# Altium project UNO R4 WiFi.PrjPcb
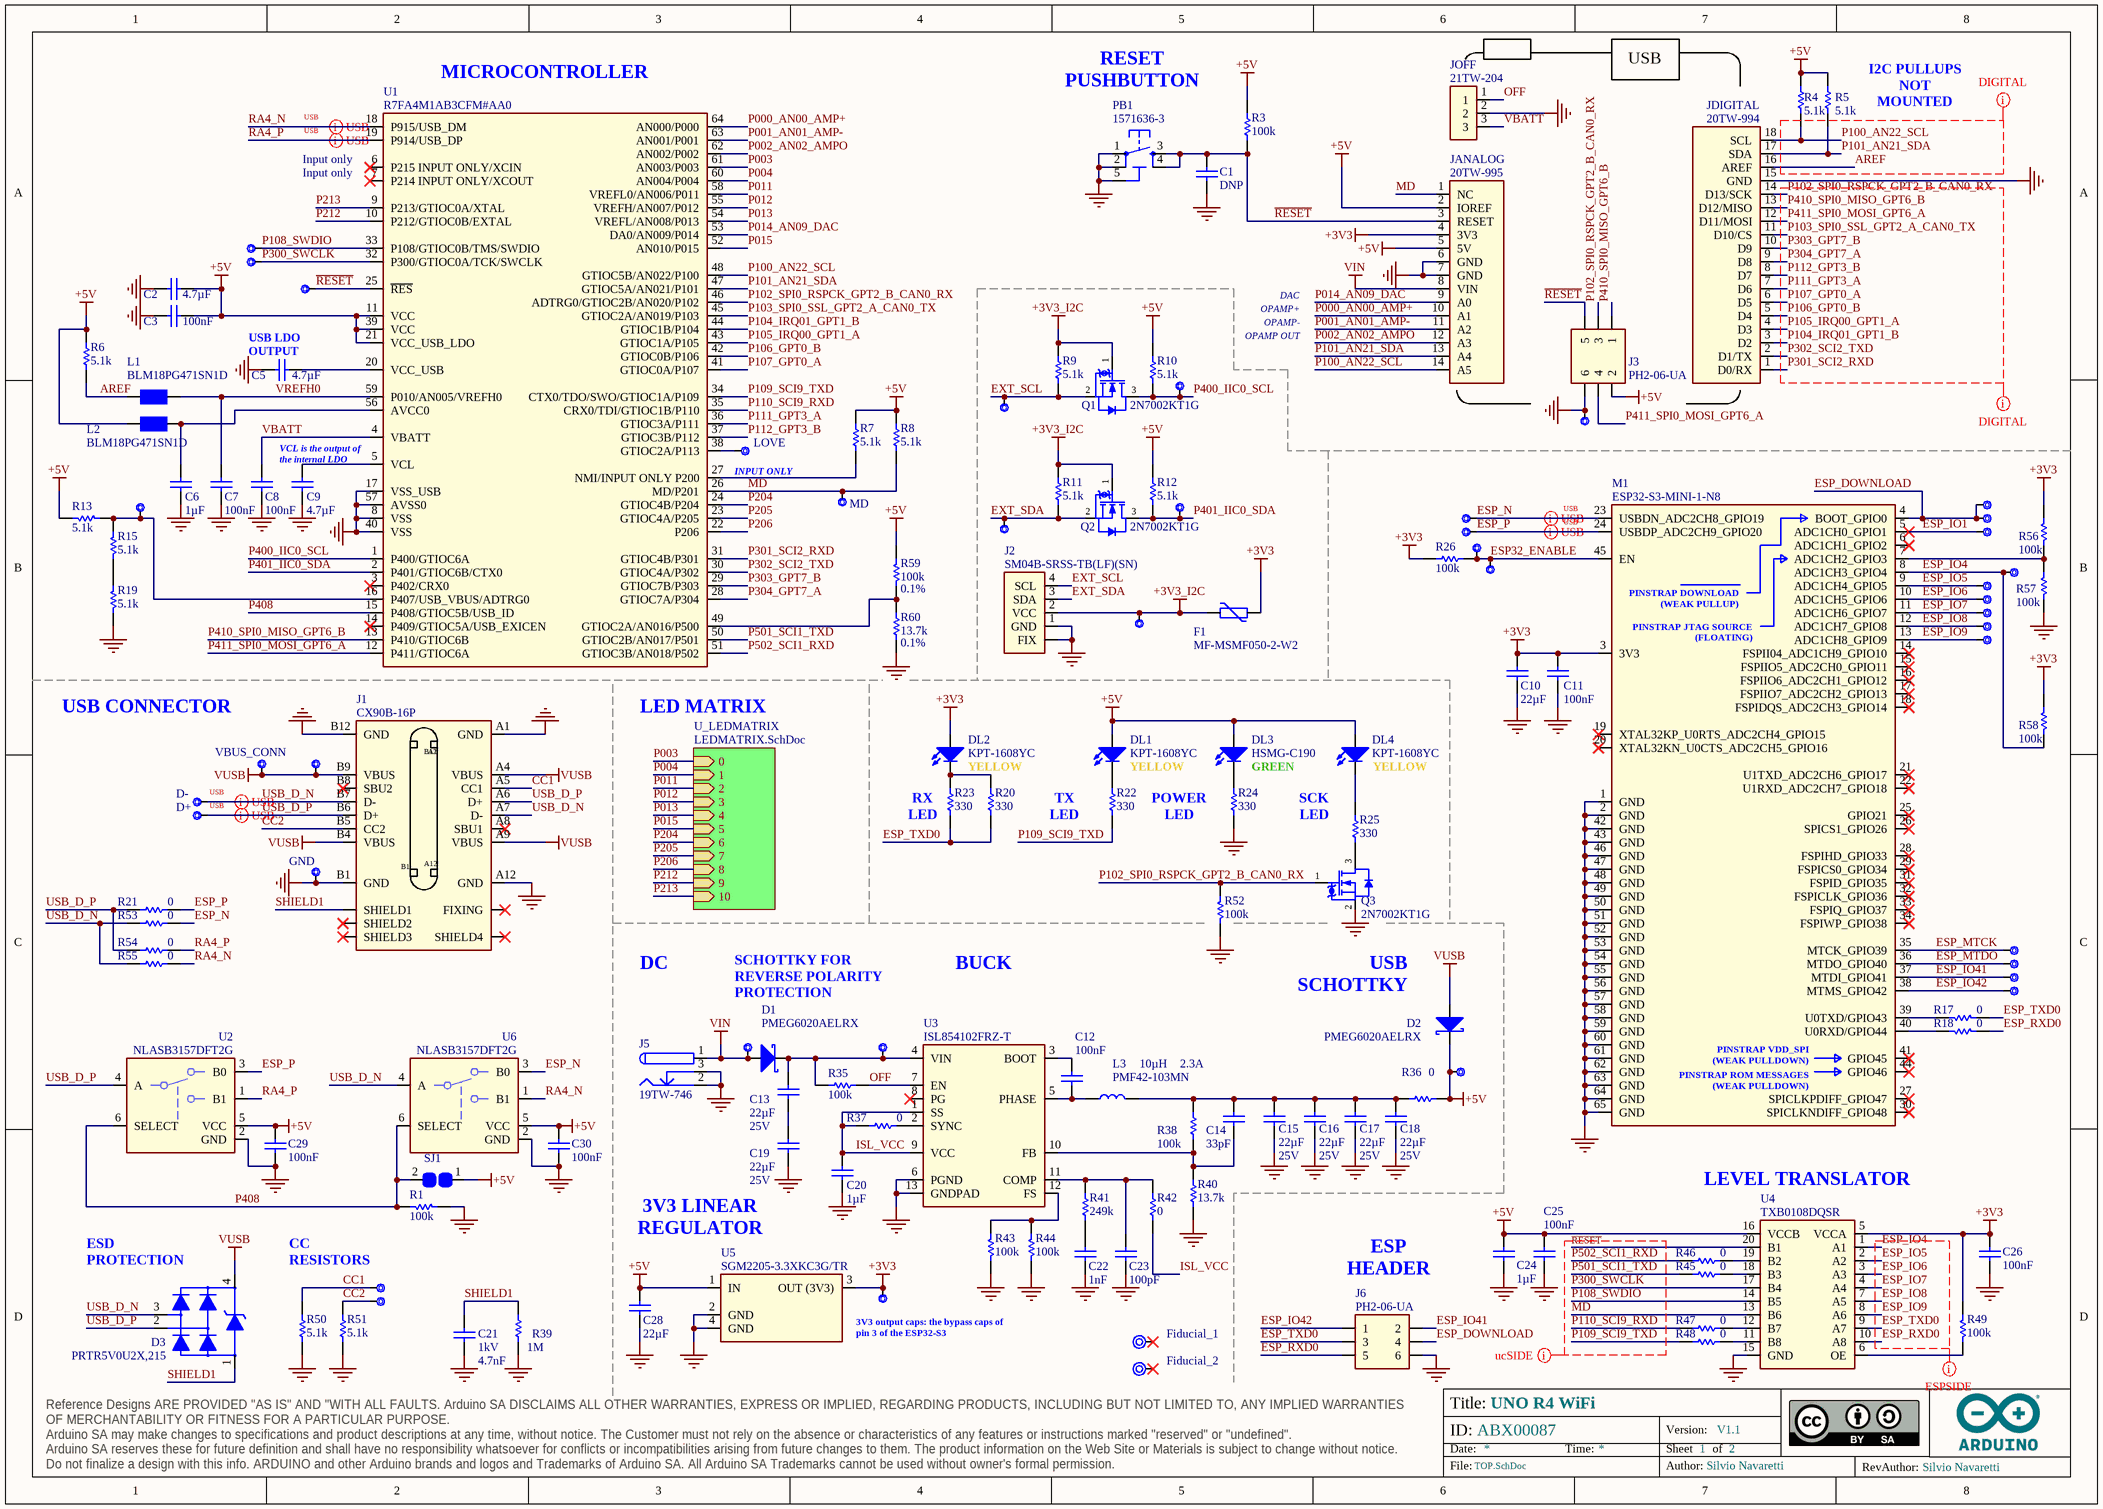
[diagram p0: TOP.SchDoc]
Version: V1.1; VIA_THROUGH_PAD_MM: 0.6; VIA_THROUGH_HOLE_MM: 0.3; VIA_THROUGH: X; VIA_5_PAD_MM: _; VIA_5_HOLE_MM: _; VIA_5: _; VIA_4_PAD_MM: _; VIA_4_HOLE_MM: _; VIA_4: _; VIA_3_PAD_MM: _; VIA_3_HOLE_MM: _; VIA_3: _; VIA_2_PAD_MM: _; VIA_2_HOLE_MM: _; VIA_2: _; VIA_1_PAD_MM: _; VIA_1_HOLE_MM: _; VIA_1: _; TRACK_MIN_WIDTH_OUTER: 0.15mm; TRACK_MIN_WIDTH_INNER: 0.15mm; SKU: ABX00087; PANEL_TABS: _; PANEL_SIZE: 284.7mm x 157.16mm; PANEL_SCORING: X; PANEL_REQUESTED: _; PANEL_PROVIDED: X; PANEL_NUMBER_OF_FIGURES: 10; PANEL_NOT_REQUESTED: _; PANEL_MILLING: X; INSULATION_MIN_OUTER: 0.15mm; INSULATION_MIN_INNER: 0.15mm; FINISH_TBD: _; FINISH_TABS: _; FINISH_SOLDERMASK_TOP: X; FINISH_SOLDERMASK_PEELABLE_TOP: _; FINISH_SOLDERMASK_PEELABLE_COLOR: _; FINISH_SOLDERMASK_PEELABLE_BOTTOM: _; FINISH_SOLDERMASK_COLOR: BLUE; FINISH_SOLDERMASK_BOTTOM: X; FINISH_SN/PB: _; FINISH_SILK_TOP: X; FINISH_SILK_COLOR: WHITE; FINISH_SILK_BOTTOM: X; FINISH_NI/AU: _; FINISH_HAL_LF: _; FINISH_HAL: _; FINISH_ENIG: X; FINISH_EDGE_PLATING: _; FINISH_ADJUSTMENTS: _; DRILLS_SOLDER_FILLING: X; DRILLS_SLOT: _; DRILLS_RESIN_FILLING: _; DRILLS_PRESSFIT: _; DRILLS_LASER: _; DRILLS_FULL: X; DRILLS_COPPER_FILLING: _; DRILLS_BURIED: _; DRILLS_BLIND: _; BOARD_INFO_THICKNESS: 1.6mm; BOARD_INFO_TBD: _; BOARD_INFO_RIGID/FLEX: _; BOARD_INFO_RIGID: X; BOARD_INFO_POLYMIDE: _; BOARD_INFO_PCB_SIZE: 68.58mm x 53.34mm; BOARD_INFO_NUMBER_OF_LAYERS: 4; BOARD_INFO_IPC_NA: X; BOARD_INFO_IPC3: _; BOARD_INFO_IPC2: _; BOARD_INFO_IPC1: _; BOARD_INFO_FR4_HTG: _; BOARD_INFO_FR4: X; BOARD_INFO_FLEX: _; BOARD_INFO_Er: _; BOARD_INFO_AUTHOR: Silvio Navaretti; ASSEMBLY_THT: X; ASSEMBLY_SMD: X; ASSEMBLY_PRESSFIT: _; ASSEMBLY_BGA: _
2 sheets, 257 parts. Net scope: hierarchical (ports join the sheet entries above them; power ports are global).
Board file: PCB.PcbDoc
Sheets:
  TOP.SchDoc
    U_LEDMATRIX = LEDMATRIX.SchDoc

## Sheet TOP.SchDoc: UNO R4 WiFi
size A3; Author: Silvio Navaretti; CompanyName: ARDUINO SRL; DrawnBy: Silvio Navaretti; Engineer: Silvio Navaretti; Organization: ARDUINO SRL; Address1: Via Agostino Da Montefeltro 2 Torino TO, Italy; DocumentNumber: ABX00087; Revision: V1.1; SheetNumber: 1; SheetTotal: 2; RevAuthor: Silvio Navaretti

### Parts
3V3_IC  CMP-018-0004-A.4  [TP-0.8MM]  (value not drawn)  (no BOM)
3V3_TOP  CMP-018-0004-A.4  [TP-0.8MM]  (value not drawn)  (no BOM)
5V_TOP  CMP-018-0004-A.4  [TP-0.8MM]  (value not drawn)  (no BOM)
BUCK_IN_TOP  CMP-018-0004-A.4  [TP-0.8MM]  (value not drawn)  (no BOM)
C1  DNP  [CAP-0402]
C2  value 4.7µF  [CAP-0603]  (hidden comment: GRM188R61C475KAAJD)
C3  value 100nF  [CAP-0402]  (hidden comment: GRM155R61H104KE19D)
C5  value 4.7µF  [CAP-0603]  (hidden comment: GRM188R61C475KAAJD)
C6  value 1µF  [CAP-0402]  (hidden comment: CL05A105KP5NNNC)
C7  value 100nF  [CAP-0402]  (hidden comment: GRM155R61H104KE19D)
C8  value 100nF  [CAP-0402]  (hidden comment: GRM155R61H104KE19D)
C9  value 4.7µF  [CAP-0603]  (hidden comment: GRM188R61C475KAAJD)
C10  value 22µF  [CAP-0805]  (hidden comment: CL21A226MAQNNNE)
C11  value 100nF  [CAP-0402]  (hidden comment: GRM155R61H104KE19D)
C12  value 100nF  [CAP-0402]  (hidden comment: GRM155R61H104KE19D)
C13  value 22µF  Voltage: 25V  [CAP-0805]  (hidden comment: CL21A226MAQNNNE)
C14  value 33pF  [CAP-0402]  (hidden comment: GRM1555C1H330JA01D)
C15  value 22µF  Voltage: 25V  [CAP-0805]  (hidden comment: CL21A226MAQNNNE)
C16  value 22µF  Voltage: 25V  [CAP-0805]  (hidden comment: CL21A226MAQNNNE)
C17  value 22µF  Voltage: 25V  [CAP-0805]  (hidden comment: CL21A226MAQNNNE)
C18  value 22µF  Voltage: 25V  [CAP-0805]  (hidden comment: CL21A226MAQNNNE)
C19  value 22µF  Voltage: 25V  [CAP-0805]  (hidden comment: CL21A226MAQNNNE)
C20  value 1µF  [CAP-0402]  (hidden comment: CL05A105KP5NNNC)
C21  value 4.7nF  Voltage: 1kV  [CAP-0805]  (hidden comment: FV21X472K102ECG)
C22  value 1nF  [CAP-0402]  (hidden comment: GRM155R71H102KA01D)
C23  value 100pF  [CAP-0402]  (hidden comment: CC0402JRNPO9BN101)
C24  value 1µF  [CAP-0402]  (hidden comment: CL05A105KP5NNNC)
C25  value 100nF  [CAP-0402]  (hidden comment: GRM155R61H104KE19D)
C26  value 100nF  [CAP-0402]  (hidden comment: GRM155R61H104KE19D)
C28  value 22µF  [CAP-0805]  (hidden comment: CL21A226MAQNNNE)
C29  value 100nF  [CAP-0402]  (hidden comment: GRM155R61H104KE19D)
C30  value 100nF  [CAP-0402]  (hidden comment: GRM155R61H104KE19D)
CC1  CMP-018-0004-A.4  [TP-0.8MM]  (value not drawn)  (no BOM)
CC2  CMP-018-0004-A.4  [TP-0.8MM]  (value not drawn)  (no BOM)
D1  PMEG6020AELRX  [SOD123-1]
D2  PMEG6020AELRX  [SOD123-1]
D3  PRTR5V0U2X,215  [SOT190P230X110-4N]
D+  CMP-018-0005-A.3  [TP-1.00MM]  (value not drawn)  (no BOM)
D+_TOP  CMP-018-0004-A.4  [TP-0.8MM]  (value not drawn)  (no BOM)
D-  CMP-018-0005-A.3  [TP-1.00MM]  (value not drawn)  (no BOM)
D-_TOP  CMP-018-0004-A.4  [TP-0.8MM]  (value not drawn)  (no BOM)
DL1  KPT-1608YC  [LEDC1608X80N-AK]
DL2  KPT-1608YC  [LEDC1608X80N-AK]
DL3  HSMG-C190  [LEDC1608X80N-AK]
DL4  KPT-1608YC  [LEDC1608X80N-AK]
ESP_DOWNLOAD_BOTTOM1  CMP-018-0005-A.3  [TP-1.00MM]  (value not drawn)  (no BOM)
ESP_DOWNLOAD_TOP  CMP-018-0004-A.4  [TP-0.8MM]  (value not drawn)  (no BOM)
ESP_EN_BOTTOM  CMP-018-0005-A.3  [TP-1.00MM]  (value not drawn)  (no BOM)
ESP_EN_TOP  CMP-018-0004-A.4  [TP-0.8MM]  (value not drawn)  (no BOM)
ESP_IO1  CMP-018-0004-A.4  [TP-0.8MM]  (value not drawn)  (no BOM)
ESP_IO4  CMP-018-0004-A.4  [TP-0.8MM]  (value not drawn)  (no BOM)
ESP_IO5  CMP-018-0004-A.4  [TP-0.8MM]  (value not drawn)  (no BOM)
ESP_IO6  CMP-018-0004-A.4  [TP-0.8MM]  (value not drawn)  (no BOM)
ESP_IO7  CMP-018-0004-A.4  [TP-0.8MM]  (value not drawn)  (no BOM)
ESP_IO8  CMP-018-0004-A.4  [TP-0.8MM]  (value not drawn)  (no BOM)
ESP_IO9  CMP-018-0004-A.4  [TP-0.8MM]  (value not drawn)  (no BOM)
ESP_MTCK  CMP-018-0004-A.4  [TP-0.8MM]  (value not drawn)  (no BOM)
ESP_MTDI  CMP-018-0004-A.4  [TP-0.8MM]  (value not drawn)  (no BOM)
ESP_MTDO  CMP-018-0004-A.4  [TP-0.8MM]  (value not drawn)  (no BOM)
ESP_MTMS  CMP-018-0004-A.4  [TP-0.8MM]  (value not drawn)  (no BOM)
EXT_SCL  CMP-018-0004-A.4  [TP-0.8MM]  (value not drawn)  (no BOM)
EXT_SDA  CMP-018-0004-A.4  [TP-0.8MM]  (value not drawn)  (no BOM)
F1  MF-MSMF050-2-W2  [1812]
Fiducial_1  Fiducial mark 1mm with 2mm solder  [Fiducial mark 1mm with circle-Footprint-1]  (value not drawn)  (no BOM)
Fiducial_2  Fiducial mark 1mm with 2mm solder  [Fiducial mark 1mm with circle-Footprint-1]  (value not drawn)  (no BOM)
GND  CMP-018-0005-A.3  [TP-1.00MM]  (value not drawn)  (no BOM)
GND2  CMP-018-0005-A.3  [TP-1.00MM]  (value not drawn)  (no BOM)
J1  CX90B-16P  [CX90B-16P-Footprint-1]
J2  SM04B-SRSS-TB(LF)(SN)  [SM04B-SRSS-TB(LF)(SN)-Footprint-1]
J3  PH2-06-UA  [2X03]
J5  19TW-746  [POWERSUPPLY_DC-21MM]
J6  PH2-06-UA  [2X03]
JANALOG  20TW-995  [1X14-CUSTOM]
JDIGITAL  20TW-994  [1X18-CUSTOM]
JOFF  21TW-204  [21TW-204]
L1  BLM18PG471SN1D  [L-0603]
L2  BLM18PG471SN1D  [L-0603]
L3  PMF42-103MN  Max DC Current: 2.3A  Inductance: 10µH  [PMF42]
LOVE  CMP-018-0005-A.3  [TP-1.00MM]  (value not drawn)  (no BOM)
M1  ESP32-S3-MINI-1-N8  [ESP32-S3-MINI-1-N8]
MD  CMP-018-0004-A.4  [TP-0.8MM]  (value not drawn)  (no BOM)
P400_SCL  CMP-018-0004-A.4  [TP-0.8MM]  (value not drawn)  (no BOM)
P401_SDA  CMP-018-0004-A.4  [TP-0.8MM]  (value not drawn)  (no BOM)
PB1  1571636-3  [TS42]
Q1  2N7002KT1G  [SOT23]
Q2  2N7002KT1G  [SOT23]
Q3  2N7002KT1G  [SOT23]
R1  value 100k  [RES-0402]  (hidden comment: CRCW0402100KFKEDC)
R3  value 100k  [RES-0402]  (hidden comment: CRCW0402100KFKEDC)
R4  value 5.1k  [RES-0402]  (hidden comment: RC0402FR-075K1L)
R5  value 5.1k  [RES-0402]  (hidden comment: RC0402FR-075K1L)
R6  value 5.1k  [RES-0402]  (hidden comment: RC0402FR-075K1L)
R7  value 5.1k  [RES-0402]  (hidden comment: RC0402FR-075K1L)
R8  value 5.1k  [RES-0402]  (hidden comment: RC0402FR-075K1L)
R9  value 5.1k  [RES-0402]  (hidden comment: RC0402FR-075K1L)
R10  value 5.1k  [RES-0402]  (hidden comment: RC0402FR-075K1L)
R11  value 5.1k  [RES-0402]  (hidden comment: RC0402FR-075K1L)
R12  value 5.1k  [RES-0402]  (hidden comment: RC0402FR-075K1L)
R13  value 5.1k  [RES-0402]  (hidden comment: RC0402FR-075K1L)
R15  value 5.1k  [RES-0402]  (hidden comment: RC0402FR-075K1L)
R17  value 0  [RES-0402]  (hidden comment: CRCW04020000Z0EDC)
R18  value 0  [RES-0402]  (hidden comment: CRCW04020000Z0EDC)
R19  value 5.1k  [RES-0402]  (hidden comment: RC0402FR-075K1L)
R20  value 330  [RES-0402]  (hidden comment: CRCW0402330RJNED)
R21  value 0  [RES-0402]  (hidden comment: CRCW04020000Z0EDC)
R22  value 330  [RES-0402]  (hidden comment: CRCW0402330RJNED)
R23  value 330  [RES-0402]  (hidden comment: CRCW0402330RJNED)
R24  value 330  [RES-0402]  (hidden comment: CRCW0402330RJNED)
R25  value 330  [RES-0402]  (hidden comment: CRCW0402330RJNED)
R26  value 100k  [RES-0402]  (hidden comment: CRCW0402100KFKEDC)
R35  value 100k  [RES-0402]  (hidden comment: CRCW0402100KFKEDC)
R36  value 0  [RES-0402]  (hidden comment: CRCW04020000Z0EDC)
R37  value 0  [RES-0402]  (hidden comment: CRCW04020000Z0EDC)
R38  value 100k  [RES-0402]  (hidden comment: CRCW0402100KFKEDC)
R39  value 1M  [RES-0402]  (hidden comment: CRCW04021M00FKED)
R40  value 13.7k  [RES-0402]  (hidden comment: RC0402FR-0713K7L)
R41  value 249k  [RES-0402]  (hidden comment: AC0402FR-07249KL)
R42  value 0  [RES-0402]  (hidden comment: CRCW04020000Z0EDC)
R43  value 100k  [RES-0402]  (hidden comment: CRCW0402100KFKEDC)
R44  value 100k  [RES-0402]  (hidden comment: CRCW0402100KFKEDC)
R45  value 0  [RES-0402]  (hidden comment: CRCW04020000Z0EDC)
R46  value 0  [RES-0402]  (hidden comment: CRCW04020000Z0EDC)
R47  value 0  [RES-0402]  (hidden comment: CRCW04020000Z0EDC)
R48  value 0  [RES-0402]  (hidden comment: CRCW04020000Z0EDC)
R49  value 100k  [RES-0402]  (hidden comment: CRCW0402100KFKEDC)
R50  value 5.1k  [RES-0402]  (hidden comment: RC0402FR-075K1L)
R51  value 5.1k  [RES-0402]  (hidden comment: RC0402FR-075K1L)
R52  value 100k  [RES-0402]  (hidden comment: CRCW0402100KFKEDC)
R53  value 0  [RES-0402]  (hidden comment: CRCW04020000Z0EDC)
R54  value 0  [RES-0402]  (hidden comment: CRCW04020000Z0EDC)
R55  value 0  [RES-0402]  (hidden comment: CRCW04020000Z0EDC)
R56  value 100k  [RES-0402]  (hidden comment: CRCW0402100KFKEDC)
R57  value 100k  [RES-0402]  (hidden comment: CRCW0402100KFKEDC)
R58  value 100k  [RES-0402]  (hidden comment: CRCW0402100KFKEDC)
R59  value 100k  Tolerance: 0.1%  [RES-0402]  (hidden comment: WF04H1003BT)
R60  value 13.7k  Tolerance: 0.1%  [RES-0402]  (hidden comment: WF04H1372BTL)
RES  CMP-018-0004-A.4  [TP-0.8MM]  (value not drawn)  (no BOM)
SJ1  SMD solder JUMPER 0805  [SJ]  (value not drawn)  (no BOM)
SWCLK  CMP-018-0004-A.4  [TP-0.8MM]  (value not drawn)  (no BOM)
SWDIO  CMP-018-0004-A.4  [TP-0.8MM]  (value not drawn)  (no BOM)
U1  R7FA4M1AB3CFM#AA0  [CQFP50P1200X1200X170-64L]
U2  NLASB3157DFT2G  [TSOP65P210X110-6N]
U3  ISL854102FRZ-T  [QFN0P300X400X100_HS-13L]
U4  TXB0108DQSR  [FP-DQS0020A-MFG]
U5  SGM2205-3.3XKC3G/TR  [SOT223-3]
U6  NLASB3157DFT2G  [TSOP65P210X110-6N]
uC_VBUS  CMP-018-0004-A.4  [TP-0.8MM]  (value not drawn)  (no BOM)
VBUS_CONN  CMP-018-0005-A.3  [TP-1.00MM]  (value not drawn)  (no BOM)
VCONN_TOP  CMP-018-0004-A.4  [TP-0.8MM]  (value not drawn)  (no BOM)
VIN_TOP  CMP-018-0004-A.4  [TP-0.8MM]  (value not drawn)  (no BOM)

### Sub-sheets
U_LEDMATRIX = LEDMATRIX.SchDoc: 0 (in), 1 (in), 2 (in), 3 (in), 4 (in), 5 (in), 6 (in), 7 (in), 8 (in), 9 (in), 10 (in)

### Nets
+3V3: 3V3_TOP.X C10.2 C11.2 C26.2 DL2.A F1.2 JANALOG.4(3V3) M1.3(3V3) R26.1 R49.2 R56.2 R58.2 U4.5(VCCA) U5.3(OUT_(3V3))
+3V3_I2C: 3V3_IC.X F1.1 J2.2(VCC) Q1.1(G) Q2.1(G) R9.1 R11.1
+5V: 5V_TOP.X C2.2 C3.2 C24.2 C25.2 C28.2 C29.2 C30.2 D2.C DL1.A DL3.A DL4.A J3.2 JANALOG.2(IOREF) JANALOG.5(5V) L2.1 R3.2 R4.2 R5.2 R6.2 R7.1 R8.1 R10.1 R12.1 R13.1 R36.2 R59.2 SJ1.1 U1.11(VCC) U1.21(VCC_USB_LDO) U1.39(VCC) U2.5(VCC) U4.16(VCCB) U5.1(IN) U6.5(VCC)
GND: C1.2 C2.1 C3.1 C5.1 C6.2 C7.1 C8.1 C9.1 C10.1 C11.1 C15.1 C16.1 C17.1 C18.1 C19.1 C20.2 C21.1 C22.1 C23.1 C24.1 C25.1 C26.1 C28.1 C29.1 C30.1 GND.X GND2.X J1.A1(GND) J1.A12(GND) J1.B1(GND) J1.B12(GND) J2.1(GND) J2.FIX J3.6 J5.2 J5.3 J6.6 JANALOG.6(GND) JANALOG.7(GND) JDIGITAL.15(GND) JOFF.2 M1.1(GND) M1.2(GND) M1.42(GND) M1.43(GND) M1.46(GND) M1.47(GND) M1.48(GND) M1.49(GND) M1.50(GND) M1.51(GND) M1.52(GND) M1.53(GND) M1.54(GND) M1.55(GND) M1.56(GND) M1.57(GND) M1.58(GND) M1.59(GND) M1.60(GND) M1.61(GND) M1.62(GND) M1.63(GND) M1.64(GND) M1.65(GND) PB1.1 PB1.2 PB1.5(5-GND) Q3.2(S) R1.1 R19.2 R24.1 R39.1 R40.1 R43.1 R44.1 R50.1 R51.1 R52.1 R57.1 R60.1 U1.8(VSS) U1.17(VSS_USB) U1.40(VSS) U1.57(AVSS0) U2.2(GND) U3.6(PGND) U3.13(GNDPAD) U4.15(GND) U5.2(GND) U5.4(GND) U6.2(GND)
VIN: D1.A J5.1 JANALOG.8(VIN) VIN_TOP.X
VUSB: D2.A D3.4 J1.A4(VBUS) J1.A9(VBUS) J1.B4(VBUS) J1.B9(VBUS) VBUS_CONN.X VCONN_TOP.X
AREF: JDIGITAL.16(AREF) L1.1 R6.1  [project net AREF_1]
CC1: CC1.X J1.A5(CC1) R50.2  [project net CC1_1]
CC2: CC2.X J1.B5(CC2) R51.2  [project net CC2_1]
ESP32_ENABLE: ESP_EN_BOTTOM.X ESP_EN_TOP.X M1.45(EN) R26.2  [project net ESP32_ENABLE_1]
ESP_DOWNLOAD: ESP_DOWNLOAD_BOTTOM1.X ESP_DOWNLOAD_TOP.X J6.4 M1.4(BOOT_GPIO0)  [project net ESP_DOWNLOAD_1]
ESP_IO1: ESP_IO1.X M1.5(ADC1CH0_GPIO1)  [project net ESP_IO1_1]
ESP_IO4: ESP_IO4.X M1.8(ADC1CH3_GPIO4) R58.1 U4.1(A1)  [project net ESP_IO4_1]
ESP_IO5: ESP_IO5.X M1.9(ADC1CH4_GPIO5) U4.2(A2)  [project net ESP_IO5_1]
ESP_IO6: ESP_IO6.X M1.10(ADC1CH5_GPIO6) U4.3(A3)  [project net ESP_IO6_1]
ESP_IO7: ESP_IO7.X M1.11(ADC1CH6_GPIO7) U4.4(A4)  [project net ESP_IO7_1]
ESP_IO8: ESP_IO8.X M1.12(ADC1CH7_GPIO8) U4.7(A5)  [project net ESP_IO8_1]
ESP_IO9: ESP_IO9.X M1.13(ADC1CH8_GPIO9) U4.8(A6)  [project net ESP_IO9_1]
ESP_IO41: ESP_MTDI.X J6.2 M1.37(MTDI_GPIO41)  [project net ESP_IO41_1]
ESP_IO42: ESP_MTMS.X J6.1 M1.38(MTMS_GPIO42)  [project net ESP_IO42_1]
ESP_MTCK: ESP_MTCK.X M1.35(MTCK_GPIO39)  [project net ESP_MTCK_1]
ESP_MTDO: ESP_MTDO.X M1.36(MTDO_GPIO40)  [project net ESP_MTDO_1]
ESP_N: D-_TOP.X M1.23(USBDN_ADC2CH8_GPIO19) R53.1 U6.3(B0)  [project net ESP_N_1]
ESP_P: D+_TOP.X M1.24(USBDP_ADC2CH9_GPIO20) R21.1 U2.3(B0)  [project net ESP_P_1]
ESP_RXD0: J6.5 R18.1 U4.10(A8)  [project net ESP_RXD0_1]
ESP_TXD0: J6.3 R17.1 R20.1 R23.1 U4.9(A7)  [project net ESP_TXD0_1]
EXT_SCL: EXT_SCL.X J2.4(SCL) Q1.2(S) R9.2  [project net EXT_SCL_1]
EXT_SDA: EXT_SDA.X J2.3(SDA) Q2.2(S) R11.2  [project net EXT_SDA_1]
ISL_VCC: C20.1 R37.2 R42.2 U3.1(SS) U3.9(VCC)  [project net ISL_VCC_1]
MD: JANALOG.1(NC) MD.X R8.2 U1.26(MD/P201) U4.13(B6)  [project net MD_1]
OFF: JOFF.1 R35.2 U3.7(EN)  [project net OFF_1]
P000_AN00_AMP+: JANALOG.10(A1) U1.64(AN000/P000)  [project net P000_AN00_AMP+_1]
P001_AN01_AMP-: JANALOG.11(A2) U1.63(AN001/P001)  [project net P001_AN01_AMP-_1]
P002_AN02_AMPO: JANALOG.12(A3) U1.62(AN002/P002)  [project net P002_AN02_AMPO_1]
P003: U1.61(AN003/P003) ; sheet U_LEDMATRIX/0
P004: U1.60(AN004/P004) ; sheet U_LEDMATRIX/1
P011: U1.58(VREFL0/AN006/P011) ; sheet U_LEDMATRIX/2
P012: U1.55(VREFH/AN007/P012) ; sheet U_LEDMATRIX/3
P013: U1.54(VREFL/AN008/P013) ; sheet U_LEDMATRIX/4
P014_AN09_DAC: JANALOG.9(A0) U1.53(DA0/AN009/P014)  [project net P014_AN09_DAC_1]
P015: U1.52(AN010/P015) ; sheet U_LEDMATRIX/5
P100_AN22_SCL: JANALOG.14(A5) JDIGITAL.18(SCL) R4.1 U1.48(GTIOC5B/AN022/P100)  [project net P100_AN22_SCL_1]
P101_AN21_SDA: JANALOG.13(A4) JDIGITAL.17(SDA) R5.1 U1.47(GTIOC5A/AN021/P101)  [project net P101_AN21_SDA_1]
P102_SPI0_RSPCK_GPT2_B_CAN0_RX: J3.3 JDIGITAL.14(D13/SCK) Q3.1(G) R52.2 U1.46(ADTRG0/GTIOC2B/AN020/P102)  [project net P102_SPI0_RSPCK_GPT2_B_CAN0_RX_1]
P103_SPI0_SSL_GPT2_A_CAN0_TX: JDIGITAL.11(D10/CS) U1.45(GTIOC2A/AN019/P103)  [project net P103_SPI0_SSL_GPT2_A_CAN0_TX_1]
P104_IRQ01_GPT1_B: JDIGITAL.3(D2) U1.44(GTIOC1B/P104)  [project net P104_IRQ01_GPT1_B_1]
P105_IRQ00_GPT1_A: JDIGITAL.4(D3) U1.43(GTIOC1A/P105)  [project net P105_IRQ00_GPT1_A_1]
P106_GPT0_B: JDIGITAL.5(D4) U1.42(GTIOC0B/P106)  [project net P106_GPT0_B_1]
P107_GPT0_A: JDIGITAL.6(D5) U1.41(GTIOC0A/P107)  [project net P107_GPT0_A_1]
P108_SWDIO: SWDIO.X U1.33(P108/GTIOC0B/TMS/SWDIO) U4.14(B5)  [project net P108_SWDIO_1]
P109_SCI9_TXD: R22.1 R48.1 U1.34(CTX0/TDO/SWO/GTIOC1A/P109)  [project net P109_SCI9_TXD_1]
P110_SCI9_RXD: R47.1 U1.35(CRX0/TDI/GTIOC1B/P110)  [project net P110_SCI9_RXD_1]
P111_GPT3_A: JDIGITAL.7(D6) U1.36(GTIOC3A/P111)  [project net P111_GPT3_A_1]
P112_GPT3_B: JDIGITAL.8(D7) U1.37(GTIOC3B/P112)  [project net P112_GPT3_B_1]
P204: U1.24(GTIOC4B/P204) ; sheet U_LEDMATRIX/6
P205: U1.23(GTIOC4A/P205) ; sheet U_LEDMATRIX/7
P206: U1.22(P206) ; sheet U_LEDMATRIX/8
P212: U1.10(P212/GTIOC0B/EXTAL) ; sheet U_LEDMATRIX/9
P213: U1.9(P213/GTIOC0A/XTAL) ; sheet U_LEDMATRIX/10
P300_SWCLK: SWCLK.X U1.32(P300/GTIOC0A/TCK/SWCLK) U4.17(B4)  [project net P300_SWCLK_1]
P301_SCI2_RXD: JDIGITAL.1(D0/RX) U1.31(GTIOC4B/P301)  [project net P301_SCI2_RXD_1]
P302_SCI2_TXD: JDIGITAL.2(D1/TX) U1.30(GTIOC4A/P302)  [project net P302_SCI2_TXD_1]
P303_GPT7_B: JDIGITAL.10(D9) U1.29(GTIOC7B/P303)  [project net P303_GPT7_B_1]
P304_GPT7_A: JDIGITAL.9(D8) U1.28(GTIOC7A/P304)  [project net P304_GPT7_A_1]
P400_IIC0_SCL: P400_SCL.X Q1.3(D) R10.2 U1.1(P400/GTIOC6A)  [project net P400_IIC0_SCL_1]
P401_IIC0_SDA: P401_SDA.X Q2.3(D) R12.2 U1.2(P401/GTIOC6B/CTX0)  [project net P401_IIC0_SDA_1]
P408: R1.2 SJ1.2 U1.15(P408/GTIOC5B/USB_ID) U2.6(SELECT) U6.6(SELECT)  [project net P408_1]
P410_SPI0_MISO_GPT6_B: J3.1 JDIGITAL.13(D12/MISO) U1.13(P410/GTIOC6B)  [project net P410_SPI0_MISO_GPT6_B_1]
P411_SPI0_MOSI_GPT6_A: J3.4 JDIGITAL.12(D11/MOSI) U1.12(P411/GTIOC6A)  [project net P411_SPI0_MOSI_GPT6_A_1]
P501_SCI1_TXD: R45.1 U1.50(GTIOC2B/AN017/P501)  [project net P501_SCI1_TXD_1]
P502_SCI1_RXD: R46.1 U1.51(GTIOC3B/AN018/P502)  [project net P502_SCI1_RXD_1]
~{RESET}: C1.1 J3.5 JANALOG.3(RESET) PB1.3 PB1.4 R3.1 RES.X U1.25(~{RES}) U4.20(B1)  [project net ~{RESET}_1]
RA4_N: R55.1 U1.18(P915/USB_DM) U6.1(B1)  [project net RA4_N_1]
RA4_P: R54.1 U1.19(P914/USB_DP) U2.1(B1)  [project net RA4_P_1]
SHIELD1: C21.2 D3.1 J1.SHIELD1 R39.2  [project net SHIELD1_1]
USB_D_N: D3.3 D-.X J1.A7(D-) J1.B7(D-) R53.2 R55.2 U6.4(A)  [project net USB_D_N_1]
USB_D_P: D3.2 D+.X J1.A6(D+) J1.B6(D+) R21.2 R54.2 U2.4(A)  [project net USB_D_P_1]
VBATT: C8.2 JOFF.3 U1.4(VBATT)  [project net VBATT_1]
VREFH0: C7.2 L1.2 U1.59(P010/AN005/VREFH0)  [project net VREFH0_1]
NetBUCK_IN_TOP_X: BUCK_IN_TOP.X C13.2 D1.C R35.1 U3.4(VIN)
NetC5_2: C5.2 U1.20(VCC_USB)
NetC6_1: C6.1 L2.2 U1.56(AVCC0)
NetC9_2: C9.2 U1.5(VCL)
NetC12_1: C12.1 L3.1 U3.5(PHASE)
NetC12_2: C12.2 U3.3(BOOT)
NetC13_1: C13.1 C19.2
NetC14_1: C14.1 R38.2 R40.2 U3.10(FB)
NetC14_2: C14.2 C15.2 C16.2 C17.2 C18.2 L3.2 R36.1 R38.1
NetC22_2: C22.2 R41.1
NetC23_2: C23.2 R41.2 R42.1 U3.11(COMP)
NetDL1_C: DL1.C R22.2
NetDL2_C: DL2.C R20.2 R23.2
NetDL3_C: DL3.C R24.2
NetDL4_C: DL4.C R25.2
NetLOVE_X: LOVE.X U1.38(GTIOC2A/P113)
NetM1_7: M1.7(ADC1CH2_GPIO3) R56.1 R57.2
NetM1_39: M1.39(U0TXD/GPIO43) R17.2
NetM1_40: M1.40(U0RXD/GPIO44) R18.2
NetQ3_3: Q3.3(D) R25.1
NetR7_2: R7.2 U1.27(NMI/INPUT_ONLY_P200)
NetR13_2: R13.2 R15.2 U1.16(P407/USB_VBUS/ADTRG0) uC_VBUS.X
NetR15_1: R15.1 R19.1
NetR37_1: R37.1 U3.2(SYNC)
NetR43_2: R43.2 R44.2 U3.12(FS)
NetR45_2: R45.2 U4.18(B3)
NetR46_2: R46.2 U4.19(B2)
NetR47_2: R47.2 U4.12(B7)
NetR48_2: R48.2 U4.11(B8)
NetR49_1: R49.1 U4.6(OE)
NetR59_1: R59.1 R60.2 U1.49(GTIOC2A/AN016/P500)

Not connected (* = marked no-connect by the designer): Fiducial_1 1*; Fiducial_2 1*; J1 A8(SBU1)* B8(SBU2)* FIXING* SHIELD2* SHIELD3* SHIELD4*; M1 6(ADC1CH1_GPIO2)* 14(FSPII04_ADC1CH9_GPIO10)* 15(FSPIIO5_ADC2CH0_GPIO11)* 16(FSPIIO6_ADC2CH1_GPIO12)* 17(FSPIIO7_ADC2CH2_GPIO13)* 18(FSPIDQS_ADC2CH3_GPIO14)* 19(XTAL32KP_U0RTS_ADC2CH4_GPIO15)* 20(XTAL32KN_U0CTS_ADC2CH5_GPIO16)* 21(U1TXD_ADC2CH6_GPIO17)* 22(U1RXD_ADC2CH7_GPIO18)* 25(GPIO21)* 26(SPICS1_GPIO26)* 27(SPICLKPDIFF_GPIO47)* 28(FSPIHD_GPIO33)* 29(FSPICS0_GPIO34)* 30(SPICLKNDIFF_GPIO48)* 31(FSPID_GPIO35)* 32(FSPICLK_GPIO36)* 33(FSPIQ_GPIO37)* 34(FSPIWP_GPIO38)* 41(GPIO45)* 44(GPIO46)*; U1 3(P402/CRX0)* 6(P215_INPUT_ONLY/XCIN)* 7(P214_INPUT_ONLY/XCOUT)* 14(P409/GTIOC5A/USB_EXICEN)*; U3 8(PG)*

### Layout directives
net class ucSIDE: MD, P108_SWDIO, P109_SCI9_TXD, P110_SCI9_RXD, P300_SWCLK, P501_SCI1_TXD, P502_SCI1_RXD, ~{RESET}
net class DIGITAL: AREF, P100_AN22_SCL, P101_AN21_SDA, P102_SPI0_RSPCK_GPT2_B_CAN0_RX, P103_SPI0_SSL_GPT2_A_CAN0_TX, P104_IRQ01_GPT1_B, P105_IRQ00_GPT1_A, P106_GPT0_B, P107_GPT0_A, P111_GPT3_A, P112_GPT3_B, P301_SCI2_RXD, P302_SCI2_TXD, P303_GPT7_B, P304_GPT7_A, P410_SPI0_MISO_GPT6_B, P411_SPI0_MOSI_GPT6_A
differential pair; differential pair class USB: ESP_N_1, ESP_P_1, RA4_N_1, RA4_P_1, USB_D_N_1, USB_D_P_1
net class espSIDE: ESP_IO4, ESP_IO5, ESP_IO6, ESP_IO7, ESP_IO8, ESP_IO9, ESP_RXD0, ESP_TXD0

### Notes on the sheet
- (near U1) MICROCONTROLLER
- (near R3) RESET PUSHBUTTON
- USB
- (near R5) I2C PULLUPS
  NOT MOUNTED
- (near U1) Input only
- DAC
- OPAMP+
- (near C5) USB LDO OUTPUT
- OPAMP-
- OPAMP OUT
- VCL is the output of the internal LDO
- (near LOVE) INPUT ONLY
- (near VBUS_CONN) USB CONNECTOR
- (near U1) LED MATRIX
- YELLOW
- GREEN
- (near DL4) YELLOW
- (near R23) RX LED
- TX LED
- (near R24) POWER LED
- (near R25) SCK LED
- DC JACK
- BUCK CONVERTER
- SCHOTTKY FOR REVERSE POLARITY PROTECTION
- USB SCHOTTKY
- LEVEL TRANSLATOR
- 3V3 LINEAR REGULATOR
- (near D3) ESD
  PROTECTION
- (near CC1) CC RESISTORS
- ESP HEADER
- 3V3 output caps: the bypass caps of pin 3 of the ESP32-S3

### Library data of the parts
3V3_IC 3V3_TOP 5V_TOP BUCK_IN_TOP CC1 CC2 D+_TOP D-_TOP ESP_DOWNLOAD_TOP ESP_EN_TOP ESP_IO1 ESP_IO4-ESP_IO9 ESP_MTCK ESP_MTDI ESP_MTDO ESP_MTMS EXT_SCL EXT_SDA MD P400_SCL P401_SDA RES SWCLK SWDIO uC_VBUS VCONN_TOP VIN_TOP = UT0012-A.4: Test point 0.8mm
C1 = UT0021-A.3
C2 C5 C9 = C0054-A.16: CAP CHIP 0603 4.7uF 10% 16V X5R; Manufacturer: Murata; Code Arduino: A5072
C3 C7 C8 C11 C12 C25 C26 C29 C30 = C0015-A.14: CAP CHIP 0402 100nF 10% 50V X5R; Manufacturer: Murata; Code Arduino: A5141
C6 C20 C24 = C0017-A.14: CAP CHIP 0402 1uF 10% 10V X5R; Manufacturer: Samsung Electro-Mechanics; Code Arduino: 0133
C10 C13 C15-C19 C28 = C0111-A.7: CAP CHIP 0805 22uF 20% 25V X5R; Manufacturer: Samsung Electro-Mechanics; Code Arduino: C0111
C14 = C0034-A.14: CAP CHIP 0402 33pF 5% 50V C0G; Manufacturer: Murata; Code Arduino: A5494
C21 = C0059-A.14: CAP CHIP 0805 4.7nF 10% 1000V X7R; Manufacturer: PSA Shenzen; Code Arduino: 0689
C22 = C0007-A.15: CAP CHIP 0402 1nF 10% 50V X7R; Manufacturer: KEMET; Code Arduino: 2321
C23 = C0013-A.4: CAP CHIP 0402 100pF 10% 50V C0G; Manufacturer: Yageo; Code Arduino: C0013; Tolerance: 5%
D1 D2 = D0026-A.6: DIODE SCHOTTKY SMD 2A 60V SOD123FL; Manufacturer: Nexperia; Manucturer Part Number 2: SS26L; Code Arduino: 2208; Forward Voltage: 0.6V; Manucturer 2: Hottech
D3 = D0025-A.5: TVS ARRAY 4LIN.8kV 1pF SOT143B; Manufacturer: Nexperia; Device Type: ESD protection; Code Arduino: 2209
D+ D- ESP_DOWNLOAD_BOTTOM1 ESP_EN_BOTTOM GND GND2 LOVE VBUS_CONN = UT0013-A.4: Test point 1.00mm
DL1 DL2 DL4 = L0008-A.5: LED SMD 0603 GIA588   8mcd 120^; Manufacturer: Kingbright; Code Arduino: 2243
DL3 = L0009-A.5: LED SMD 0603 GREEN/568 15mcd 120^; Manufacturer: Broadcom; Code Arduino: 2204
F1 = P0002-A.7: PTC RESET FUSE 15V 500MA 1812 LOGO OO ARDUINO; Manufacturer: Bourns; Approvals: UL,CSA,TUV; Time to Trip: 0.15s; Max Current Rating: 100A; Trip Current: 1A; Resistance: 150mR; Code Arduino: 3335; Power Dissipation: 800mW
Fiducial_1 Fiducial_2 = UT0024-A.6
J1 = J0272-A.3: CONN RCPT USB3.1 TYPEC 16POS SMD; Manufacturer: Hirose; Code Arduino: J0272
J2 = J0005-A.2: CONN JST 4POS SIDE 1MM TIN QWIIC; Code Arduino: J0005
J3 J6 = J0004-A.5: CONN Header Through Hole 6 position 0.100" (2.54mm); Manufacturer: Adam Tech; Code Arduino: 0114
J5 = J0236-A.5: CONN PWR JACK 2.1X5.5MM SOLDER; Manufacturer: 4UCON; Code Arduino: 0018
JANALOG = J0063-A.7: CONN STRIP F/1/D 14v SER.NERA s1pin; Manufacturer: 4UCONN; Code Arduino: 3649
JDIGITAL = J0035-A.10: CONN STRIP F/1/D 18v SER.NERA s1pin; Manufacturer: 4UCONN; Code Arduino: 3648
JOFF = J0184-A.7: CONN HEADER VERT 3POS 2.54MM; Manufacturer: 4UCONN; Number of Contacts: 3; Insulation Resistance: 1GR; Connector Type: BOARD CONNECTOR; Contact Resistance: 20mR; Code Arduino: J0184
L1 L2 = I0006-A.5: FERRITE SMD 0603 470R 1A 0.2R; Manufacturer: Murata; Test Frequency: 100MHz; Code Arduino: 2200; Tolerance: 25%; DC Resistance (DCR): 200mR
L3 = I0072-A.3: IND 10uH 20%, max 235mR, IDC 2.3A, Isat 2.3A, shielded, max 5MHz, 4.5x4.5x1.8mm; Manufacturer: K-WELL; DC Resistance (DCR): 235m; Code Arduino: I0072
M1 = M0017-A.7: MODULE ESP32-S3 dual core 32b Xtensa LX7, WiFi 2.4GHz, BLE 5 LE, internal 8MB QSPI flash, no internal PSRAM, PCB antenna, max 85°C, 15.4x20.5x2.4mm; Manufacturer: Espressif; Code Arduino: M0017
PB1 = B0005-A.8: PUSHBUTTON SMD 6x6 5 PINS; Manufacturer: TE Connectivity; Code Arduino: 0946
Q1-Q3 = T0004-A.7: MOSFET N-CH 60V 300mA ESD prot. SOT23; Manufacturer: On Semiconductor; Device Type: Mosfet N-CH SMD; Code Arduino: A5393
R1 R3 R43 R44 R49 R52 R56-R58 = R0001-A.23: RES CHIP 0402 100k 1% 1/16W; Manufacturer: Vishay; Code Arduino: 0134; Power: 62.5mW; Temperature coefficient: 100ppm
R4-R13 R15 R19 = R0210-A.18: RES CHIP 0402 5k1 1% 1/16W; Manufacturer: YAGEO; Power: 63mW; Code Arduino: R0210; Temperature coefficient: 100ppm
R17 R18 R21 R37 R42 R45-R48 R53-R55 = R0000-A.23: RES CHIP 0402 0R 1/16W; Manufacturer: Vishay; Code Arduino: 0039; Power: 62.5mW; Tolerance: 0%; Temperature coefficient: 0ppm
R20 R22-R25 = R0017-A.23: RES CHIP 0402 330R 5% 1/16W; Manufacturer: Vishay; Code Arduino: 2229; Power: 62.5mW; Temperature coefficient: 200ppm
R26 R35 R38 = R0001-A.23: RES CHIP 0402 100k 1% 1/16W; Manufacturer: Vishay; Power: 62.5mW; Code Arduino: 0134; Temperature coefficient: 100ppm
R36 = R0000-A.23: RES CHIP 0402 0R 1/16W; Manufacturer: Vishay; Code Arduino: 0039; Tolerance: 0%; Power: 62.5mW; Temperature coefficient: 0ppm
R39 = R0058-A.23: RES CHIP 0402 1M 1% 1/16W; Manufacturer: Vishay; Power: 62.5mW; Code Arduino: 0139; Temperature coefficient: 100ppm
R40 = R0233-A.9: RES CHIP 0402 13k7 1% 1/16W; Manufacturer: YAGEO; Power: 62.5mW; Code Arduino: R0233; Temperature coefficient: 100ppm
R41 = R0234-A.8: RES CHIP 0402 249k 1% 1/16W; Manufacturer: YAGEO; Code Arduino: R0234; Power: 62.5mW; Temperature coefficient: 100ppm
R50 R51 = R0210-A.18: RES CHIP 0402 5k1 1% 1/16W; Manufacturer: YAGEO; Code Arduino: R0210; Power: 63mW; Temperature coefficient: 100ppm
R59 = R0247-A.4: RES CHIP 0402 100k 0.1% 100ppm 1/16W; Manufacturer: Walsin; Code Arduino: R0247; Power: 62.5mW
R60 = R0248-A.3: RES CHIP 0402 13k7 0.1% 100PPM 1/16W; Manufacturer: Walsin; Power: 62.5mW; Code Arduino: R0248; Temperature coefficient: 200ppm
SJ1 = UT0002-A.5: Solder Jumper 0805 THIS IS NOT A COMPONENT
U1 = U0274-A.7: IC uC RA4M1 32b M4 48MHz 254KB flash 32KB RAM 105°C LQFP64 10x10mm; Manufacturer: Renesas; Code Arduino: U0274
U2 U6 = U0174-A.2: IC SPDT,max 25R at VCC 4.5V tPD 1.2ns VCC 1.65V to 5V Iq max 10uA SOT363; Manufacturer: ON Semiconductor; Code Arduino: U0174
U3 = U0275-A.5: IC BUCK Vin 40V Iout 1.2A 2MHz 12DFN 3x4mm; Manufacturer: Renesas; Code Arduino: U0275
U4 = U0276-A.5: IC TRANSLATOR LEVEL SHIFTER BIDIR 8BIT 20SON; Manufacturer: Texas Instruments; Code Arduino: U0276
U5 = U0289-A.2: IC LINEAR REGULATOR Vout 3V3 fixed Vin max 20V Iout max 800mA Pd 1.32W; Manufacturer: SGMICRO; Code Arduino: U0289

## Sheet LEDMATRIX.SchDoc: LED MATRIX
size A4; Author: Silvio Navaretti; CompanyName: ARDUINO SRL; DrawnBy: Silvio Navaretti; Engineer: Silvio Navaretti; Organization: ARDUINO SRL; DocumentNumber: ABX00087; Revision: V1.1; SheetNumber: 2; SheetTotal: 2; RevAuthor: Silvio Navaretti
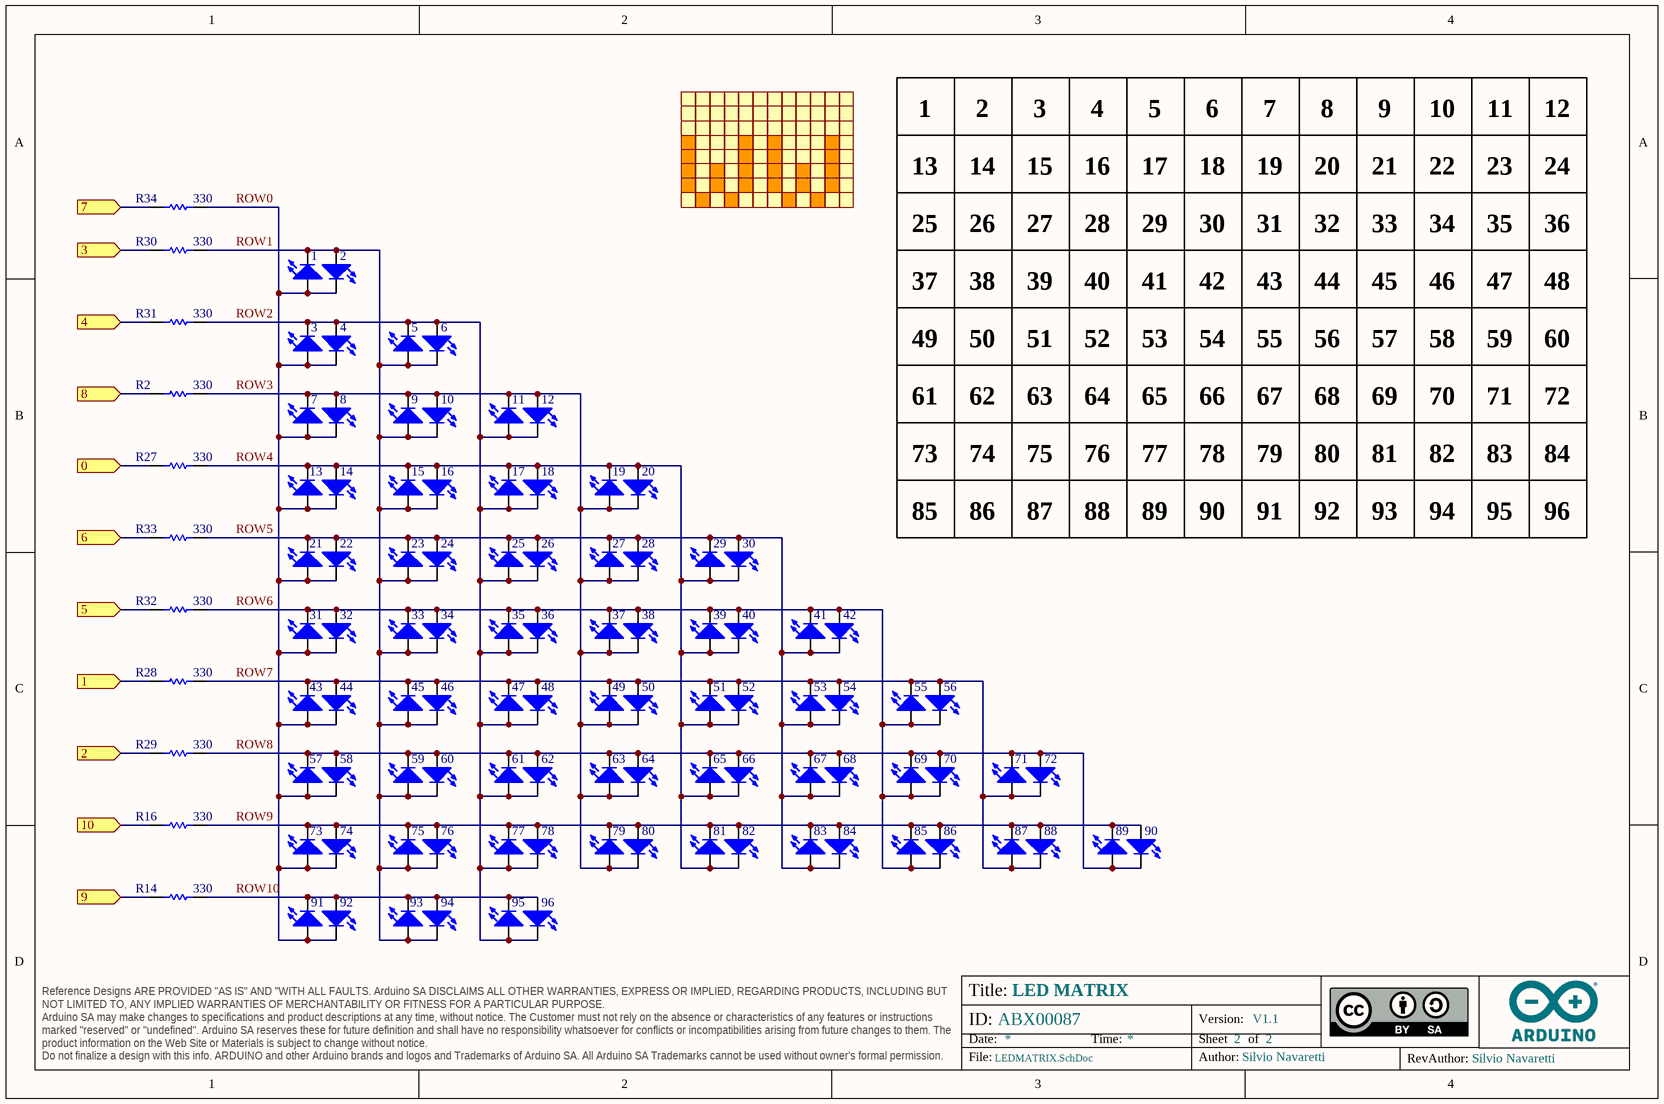
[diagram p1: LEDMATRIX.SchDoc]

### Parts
1  XHY-STB0603SR  [LEDC1608X80N-AK]  (value not drawn)
2  XHY-STB0603SR  [LEDC1608X80N-AK]  (value not drawn)
3  XHY-STB0603SR  [LEDC1608X80N-AK]  (value not drawn)
4  XHY-STB0603SR  [LEDC1608X80N-AK]  (value not drawn)
5  XHY-STB0603SR  [LEDC1608X80N-AK]  (value not drawn)
6  XHY-STB0603SR  [LEDC1608X80N-AK]  (value not drawn)
7  XHY-STB0603SR  [LEDC1608X80N-AK]  (value not drawn)
8  XHY-STB0603SR  [LEDC1608X80N-AK]  (value not drawn)
9  XHY-STB0603SR  [LEDC1608X80N-AK]  (value not drawn)
10  XHY-STB0603SR  [LEDC1608X80N-AK]  (value not drawn)
11  XHY-STB0603SR  [LEDC1608X80N-AK]  (value not drawn)
12  XHY-STB0603SR  [LEDC1608X80N-AK]  (value not drawn)
13  XHY-STB0603SR  [LEDC1608X80N-AK]  (value not drawn)
14  XHY-STB0603SR  [LEDC1608X80N-AK]  (value not drawn)
15  XHY-STB0603SR  [LEDC1608X80N-AK]  (value not drawn)
16  XHY-STB0603SR  [LEDC1608X80N-AK]  (value not drawn)
17  XHY-STB0603SR  [LEDC1608X80N-AK]  (value not drawn)
18  XHY-STB0603SR  [LEDC1608X80N-AK]  (value not drawn)
19  XHY-STB0603SR  [LEDC1608X80N-AK]  (value not drawn)
20  XHY-STB0603SR  [LEDC1608X80N-AK]  (value not drawn)
21  XHY-STB0603SR  [LEDC1608X80N-AK]  (value not drawn)
22  XHY-STB0603SR  [LEDC1608X80N-AK]  (value not drawn)
23  XHY-STB0603SR  [LEDC1608X80N-AK]  (value not drawn)
24  XHY-STB0603SR  [LEDC1608X80N-AK]  (value not drawn)
25  XHY-STB0603SR  [LEDC1608X80N-AK]  (value not drawn)
26  XHY-STB0603SR  [LEDC1608X80N-AK]  (value not drawn)
27  XHY-STB0603SR  [LEDC1608X80N-AK]  (value not drawn)
28  XHY-STB0603SR  [LEDC1608X80N-AK]  (value not drawn)
29  XHY-STB0603SR  [LEDC1608X80N-AK]  (value not drawn)
30  XHY-STB0603SR  [LEDC1608X80N-AK]  (value not drawn)
31  XHY-STB0603SR  [LEDC1608X80N-AK]  (value not drawn)
32  XHY-STB0603SR  [LEDC1608X80N-AK]  (value not drawn)
33  XHY-STB0603SR  [LEDC1608X80N-AK]  (value not drawn)
34  XHY-STB0603SR  [LEDC1608X80N-AK]  (value not drawn)
35  XHY-STB0603SR  [LEDC1608X80N-AK]  (value not drawn)
36  XHY-STB0603SR  [LEDC1608X80N-AK]  (value not drawn)
37  XHY-STB0603SR  [LEDC1608X80N-AK]  (value not drawn)
38  XHY-STB0603SR  [LEDC1608X80N-AK]  (value not drawn)
39  XHY-STB0603SR  [LEDC1608X80N-AK]  (value not drawn)
40  XHY-STB0603SR  [LEDC1608X80N-AK]  (value not drawn)
41  XHY-STB0603SR  [LEDC1608X80N-AK]  (value not drawn)
42  XHY-STB0603SR  [LEDC1608X80N-AK]  (value not drawn)
43  XHY-STB0603SR  [LEDC1608X80N-AK]  (value not drawn)
44  XHY-STB0603SR  [LEDC1608X80N-AK]  (value not drawn)
45  XHY-STB0603SR  [LEDC1608X80N-AK]  (value not drawn)
46  XHY-STB0603SR  [LEDC1608X80N-AK]  (value not drawn)
47  XHY-STB0603SR  [LEDC1608X80N-AK]  (value not drawn)
48  XHY-STB0603SR  [LEDC1608X80N-AK]  (value not drawn)
49  XHY-STB0603SR  [LEDC1608X80N-AK]  (value not drawn)
50  XHY-STB0603SR  [LEDC1608X80N-AK]  (value not drawn)
51  XHY-STB0603SR  [LEDC1608X80N-AK]  (value not drawn)
52  XHY-STB0603SR  [LEDC1608X80N-AK]  (value not drawn)
53  XHY-STB0603SR  [LEDC1608X80N-AK]  (value not drawn)
54  XHY-STB0603SR  [LEDC1608X80N-AK]  (value not drawn)
55  XHY-STB0603SR  [LEDC1608X80N-AK]  (value not drawn)
56  XHY-STB0603SR  [LEDC1608X80N-AK]  (value not drawn)
57  XHY-STB0603SR  [LEDC1608X80N-AK]  (value not drawn)
58  XHY-STB0603SR  [LEDC1608X80N-AK]  (value not drawn)
59  XHY-STB0603SR  [LEDC1608X80N-AK]  (value not drawn)
60  XHY-STB0603SR  [LEDC1608X80N-AK]  (value not drawn)
61  XHY-STB0603SR  [LEDC1608X80N-AK]  (value not drawn)
62  XHY-STB0603SR  [LEDC1608X80N-AK]  (value not drawn)
63  XHY-STB0603SR  [LEDC1608X80N-AK]  (value not drawn)
64  XHY-STB0603SR  [LEDC1608X80N-AK]  (value not drawn)
65  XHY-STB0603SR  [LEDC1608X80N-AK]  (value not drawn)
66  XHY-STB0603SR  [LEDC1608X80N-AK]  (value not drawn)
67  XHY-STB0603SR  [LEDC1608X80N-AK]  (value not drawn)
68  XHY-STB0603SR  [LEDC1608X80N-AK]  (value not drawn)
69  XHY-STB0603SR  [LEDC1608X80N-AK]  (value not drawn)
70  XHY-STB0603SR  [LEDC1608X80N-AK]  (value not drawn)
71  XHY-STB0603SR  [LEDC1608X80N-AK]  (value not drawn)
72  XHY-STB0603SR  [LEDC1608X80N-AK]  (value not drawn)
73  XHY-STB0603SR  [LEDC1608X80N-AK]  (value not drawn)
74  XHY-STB0603SR  [LEDC1608X80N-AK]  (value not drawn)
75  XHY-STB0603SR  [LEDC1608X80N-AK]  (value not drawn)
76  XHY-STB0603SR  [LEDC1608X80N-AK]  (value not drawn)
77  XHY-STB0603SR  [LEDC1608X80N-AK]  (value not drawn)
78  XHY-STB0603SR  [LEDC1608X80N-AK]  (value not drawn)
79  XHY-STB0603SR  [LEDC1608X80N-AK]  (value not drawn)
80  XHY-STB0603SR  [LEDC1608X80N-AK]  (value not drawn)
81  XHY-STB0603SR  [LEDC1608X80N-AK]  (value not drawn)
82  XHY-STB0603SR  [LEDC1608X80N-AK]  (value not drawn)
83  XHY-STB0603SR  [LEDC1608X80N-AK]  (value not drawn)
84  XHY-STB0603SR  [LEDC1608X80N-AK]  (value not drawn)
85  XHY-STB0603SR  [LEDC1608X80N-AK]  (value not drawn)
86  XHY-STB0603SR  [LEDC1608X80N-AK]  (value not drawn)
87  XHY-STB0603SR  [LEDC1608X80N-AK]  (value not drawn)
88  XHY-STB0603SR  [LEDC1608X80N-AK]  (value not drawn)
89  XHY-STB0603SR  [LEDC1608X80N-AK]  (value not drawn)
90  XHY-STB0603SR  [LEDC1608X80N-AK]  (value not drawn)
91  XHY-STB0603SR  [LEDC1608X80N-AK]  (value not drawn)
92  XHY-STB0603SR  [LEDC1608X80N-AK]  (value not drawn)
93  XHY-STB0603SR  [LEDC1608X80N-AK]  (value not drawn)
94  XHY-STB0603SR  [LEDC1608X80N-AK]  (value not drawn)
95  XHY-STB0603SR  [LEDC1608X80N-AK]  (value not drawn)
96  XHY-STB0603SR  [LEDC1608X80N-AK]  (value not drawn)
R2  value 330  [RES-0402]  (hidden comment: CRCW0402330RJNED)
R14  value 330  [RES-0402]  (hidden comment: CRCW0402330RJNED)
R16  value 330  [RES-0402]  (hidden comment: CRCW0402330RJNED)
R27  value 330  [RES-0402]  (hidden comment: CRCW0402330RJNED)
R28  value 330  [RES-0402]  (hidden comment: CRCW0402330RJNED)
R29  value 330  [RES-0402]  (hidden comment: CRCW0402330RJNED)
R30  value 330  [RES-0402]  (hidden comment: CRCW0402330RJNED)
R31  value 330  [RES-0402]  (hidden comment: CRCW0402330RJNED)
R32  value 330  [RES-0402]  (hidden comment: CRCW0402330RJNED)
R33  value 330  [RES-0402]  (hidden comment: CRCW0402330RJNED)
R34  value 330  [RES-0402]  (hidden comment: CRCW0402330RJNED)

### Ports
0 (in), 1 (in), 2 (in), 3 (in), 4 (in), 5 (in), 6 (in), 7 (in), 8 (in), 9 (in), 10 (in)

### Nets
P003: R27.2 ; port 0
P004: R28.2 ; port 1
P011: R29.2 ; port 2
P012: R30.2 ; port 3
P013: R31.2 ; port 4
P015: R32.2 ; port 5
P204: R33.2 ; port 6
P205: R34.2 ; port 7
P206: R2.2 ; port 8
P212: R14.2 ; port 9
P213: R16.2 ; port 10
ROW0: 1.A 2.C 3.A 4.C 7.A 8.C 13.A 14.C 21.A 22.C 31.A 32.C 43.A 44.C 57.A 58.C 73.A 74.C 91.A 92.C R34.1  [project net ROW0_2]
ROW1: 1.C 2.A 5.A 6.C 9.A 10.C 15.A 16.C 23.A 24.C 33.A 34.C 45.A 46.C 59.A 60.C 75.A 76.C 93.A 94.C R30.1  [project net ROW1_2]
ROW2: 3.C 4.A 5.C 6.A 11.A 12.C 17.A 18.C 25.A 26.C 35.A 36.C 47.A 48.C 61.A 62.C 77.A 78.C 95.A 96.C R31.1  [project net ROW2_2]
ROW3: 7.C 8.A 9.C 10.A 11.C 12.A 19.A 20.C 27.A 28.C 37.A 38.C 49.A 50.C 63.A 64.C 79.A 80.C R2.1  [project net ROW3_2]
ROW4: 13.C 14.A 15.C 16.A 17.C 18.A 19.C 20.A 29.A 30.C 39.A 40.C 51.A 52.C 65.A 66.C 81.A 82.C R27.1  [project net ROW4_2]
ROW5: 21.C 22.A 23.C 24.A 25.C 26.A 27.C 28.A 29.C 30.A 41.A 42.C 53.A 54.C 67.A 68.C 83.A 84.C R33.1  [project net ROW5_2]
ROW6: 31.C 32.A 33.C 34.A 35.C 36.A 37.C 38.A 39.C 40.A 41.C 42.A 55.A 56.C 69.A 70.C 85.A 86.C R32.1  [project net ROW6_2]
ROW7: 43.C 44.A 45.C 46.A 47.C 48.A 49.C 50.A 51.C 52.A 53.C 54.A 55.C 56.A 71.A 72.C 87.A 88.C R28.1  [project net ROW7_2]
ROW8: 57.C 58.A 59.C 60.A 61.C 62.A 63.C 64.A 65.C 66.A 67.C 68.A 69.C 70.A 71.C 72.A 89.A 90.C R29.1  [project net ROW8_2]
ROW9: 73.C 74.A 75.C 76.A 77.C 78.A 79.C 80.A 81.C 82.A 83.C 84.A 85.C 86.A 87.C 88.A 89.C 90.A R16.1  [project net ROW9_2]
ROW10: 91.C 92.A 93.C 94.A 95.C 96.A R14.1  [project net ROW10_2]

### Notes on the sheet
- 1
- 2
- 3
- 4
- 5
- 6
- 7
- 8
- 9
- 10
- 11
- 12
- 13
- 14
- 15
- 16
- 17
- 18
- 19
- 20
- 21
- 22
- 23
- 24
- 25
- 26
- 27
- 28
- 29
- 30
- 31
- 32
- 33
- 34
- 35
- 36
- 37
- 38
- 39
- 40
- 41
- 42
- 43
- 44
- 45
- 46
- 47
- 48
- 49
- 61
- 50
- 62
- 51
- 63
- 52
- 64
- 53
- 65
- 54
- 66
- 55
- 67
- 56
- 68
- 57
- 69
- 58
- 70
- 59
- 71
- 60
- 72
- 73
- 74
- 75
- 76
- 77
- 78
- 79
- 80
- 81
- 82
- 83
- 84
- 85
- 86
- 87
- 88
- 89
- 90
- 91
- 92
- 93
- 94
- 95
- 96

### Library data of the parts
1-96 = L0024-A.4: LED SMD 0603 RED 625nm, water clear, 42 to 88 mcd, 120 degrees, 1.6x0.8x0.6mm; Manufacturer: Shenzen Corehy Technology; Code Arduino: L0024
R2 R14 R16 R27-R34 = R0017-A.21: RES CHIP 0402 330R 5% 1/16W; Manufacturer: Vishay; Code Arduino: 2229; Power: 62.5mW; Temperature Coefficient: 200ppm

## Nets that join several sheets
P003: TOP (U1.61), LEDMATRIX (R27.2)
P004: TOP (U1.60), LEDMATRIX (R28.2)
P011: TOP (U1.58), LEDMATRIX (R29.2)
P012: TOP (U1.55), LEDMATRIX (R30.2)
P013: TOP (U1.54), LEDMATRIX (R31.2)
P015: TOP (U1.52), LEDMATRIX (R32.2)
P204: TOP (U1.24), LEDMATRIX (R33.2)
P205: TOP (U1.23), LEDMATRIX (R34.2)
P206: TOP (U1.22), LEDMATRIX (R2.2)
P212: TOP (U1.10), LEDMATRIX (R14.2)
P213: TOP (U1.9), LEDMATRIX (R16.2)

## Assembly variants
ABX00087: not fitted C1 C22 C23 R4 R5 R8 R21 R37 R41 R53 R54 R55 R56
